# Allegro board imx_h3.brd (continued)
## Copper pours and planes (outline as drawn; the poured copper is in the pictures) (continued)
GND on GND1: 0.15,0.35 0.15,19.29 4.65,19.29 4.65,28.95 0.2,28.95 0.2,60.94 4.7,60.94 4.7,70.63 0.3,70.63 0.3,81.15 4.7,81.15 4.7,81.14 62.81,81.14 62.81,90.02 91.19,90.02 91.19,104.8 109.62,104.8 109.62,54.25 123.5,54.25 123.5,0.31 23.95,0.31 23.95,1.84 16.66,1.84 16.66,0.35 ; 3 cut-outs
GND on INT1: 0.15,0.35 0.15,19.3 4.65,19.3 4.65,28.95 0.2,28.95 0.2,60.97 4.7,60.97 4.7,70.62 0.3,70.62 0.3,81.14 62.81,81.14 62.81,90.02 91.19,90.02 91.19,104.8 109.62,104.8 109.62,54.25 123.5,54.25 123.5,0.31 23.95,0.31 23.95,1.84 16.66,1.84 16.66,0.35 ; 60 cut-outs
GND on PWR: 4.7,60.97 4.7,70.62 0.3,70.62 0.3,81.15 11.87,81.15 11.87,81.14 62.78,81.14 62.78,90.03 70.05,90.03 70.05,73.72 30.12,73.72 26.55,70.14 26.55,69.51 11.58,69.51 11.58,54.67 10.75,54.67 10.75,12.21 4.41,12.21 4.41,0.35 0.15,0.35 0.15,19.31 4.65,19.31 4.65,28.95 0.2,28.94 0.2,60.97
GND on PWR: 23.94,0.3 23.94,1.85 20.04,1.85 20.04,13.74 44.77,13.74 44.77,4.1 55.62,4.1 55.62,6.47 78.15,6.47 78.15,0.3
GND on GND2: 0.3,0.35 0.3,19.31 4.65,19.31 4.65,28.96 0.2,28.96 0.2,60.97 4.85,60.97 4.85,70.62 0.3,70.62 0.3,81.14 62.78,81.14 62.78,90.08 91.19,90.08 91.19,104.8 109.62,104.8 109.62,54.21 123.5,54.21 123.5,0.31 23.95,0.31 23.95,1.85 16.65,1.85 16.65,0.35 ; 3 cut-outs
VBUS_OTG on TOP: 84,11.14 84,3.37 86.36,3.37 86.36,11.14
VBUS_OTG on PWR: 78.23,0.3 78.23,6.47 86.38,6.47 86.38,3.3 98.83,3.3 98.83,18.03 104.78,18.03 104.78,26.39 104.83,26.39 104.83,33.34 100.34,33.34 100.34,45.94 102.95,48.54 102.95,54.13 104.04,54.13 104.04,63.47 105.22,63.47 105.22,36.82 123.37,36.82 123.37,0.3
VDD_4P2 on TOP: 62.87,36.51 65.04,34.34 65.04,33.56 65.37,33.24 65.79,33.24 66.35,32.68 66.35,32.16 64.03,32.16 63.68,32.52 63.68,34.29 62.94,35.03 62.94,35.04 62.07,35.91 61.27,35.91 61.27,36.51
(no net) on BOTTOM: 0.15,0.35 0.15,19.29 4.65,19.29 4.65,28.95 0.2,28.95 0.2,60.94 4.7,60.94 4.7,70.63 0.3,70.63 0.3,81.15 4.7,81.15 4.7,81.14 62.81,81.14 62.81,90.02 91.19,90.02 91.19,104.8 109.62,104.8 109.62,54.25 123.5,54.25 123.5,0.31 23.95,0.31 23.95,1.84 16.66,1.84 16.66,0.35 ; 78 cut-outs
DCDC_VDDA_1V8 on TOP: 76,56.55 76,45.25 77.18,45.25 77.18,56.55
DCDC_VDDA_1V8 on TOP: 58.8,45.37 58.8,42.38 60.65,42.38 60.65,46.2 59.63,46.2
DCDC_VDDA_1V8 on TOP: 54.75,46.9 54.75,43.84 56.66,43.84 56.66,46.9
DCDC_VDDA_1V8 on BOTTOM: 71.39,58.44 71.39,58.23 72.28,57.34 73.41,57.34 74,56.75 74.84,56.75 75.53,56.06 75.53,44.06 77.46,44.06 77.46,55.74 74.75,58.44
DCDC_VDDA_1V8 on PWR: 53.43,41.57 53.43,46.59 56.24,46.59 57.4,47.74 57.4,48.4 57.12,48.69 57.12,53.31 56.72,53.71 56.72,55.35 56.79,55.43 56.79,58.31 58.88,58.31 61.16,60.59 76.73,60.59 76.73,58.56 79.4,55.89 79.4,45.62 75.68,41.9 72.23,41.9 70.99,43.13 64.44,43.13 62.87,41.57
DCDC_VDDD_1V2 on TOP: 57.53,46.84 57.53,44.62 58.39,44.62 58.39,45 59.23,45.84 59.23,46.76 59.2,46.79 58.5,46.79 58.39,46.68 58.39,46.84
DCDC_VDDD_1V2 on INT1: 58.59,41.31 58.93,41.31 63.63,36.61 72.91,36.61 72.91,41.31 68.36,41.31 67.66,42.01 67.66,47.5 59.84,47.5 59.84,47.5 59.54,47.5 59.54,47.6 58.73,48.41 56.55,48.41 56.55,44.44 58.59,42.39 ; 4 cut-outs
DCDC_VDDIO_3V3 on TOP: 63.48,51.12 64.58,51.12 65.09,50.61 67.86,50.61 67.86,43.63 61.6,43.63 61.6,44.2 63.05,44.2 63.05,49.1 62.99,49.16 62.99,50.63
DCDC_VDDIO_3V3 on TOP: 64.68,62.93 64.68,56.78 50.71,56.78 50.71,62.93 ; 3 cut-outs
DCDC_VDDIO_3V3 on TOP: 54.65,48.48 54.65,48.46 54.51,48.31 54.51,47.43 54.74,47.2 56.59,47.2 56.59,47.79 57.42,47.79 57.42,48.31 57.09,48.31 56.45,48.95 56.01,48.95 55.77,48.71 55.54,48.71 55.31,48.48
DCDC_VDDIO_3V3 on TOP: 95.08,44.47 98.65,48.05 99.5,48.05 102.75,51.3 102.75,51.95 103.7,51.95 103.7,47.75 102.55,46.6 101.05,46.6 97,42.55
DCDC_VDDIO_3V3 on BOTTOM: 26.34,47.16 26.34,48.97 31.3,53.93 33.54,53.93 37.85,58.25 45.36,58.25 47.66,55.94 47.66,49.77 39.13,49.77 39.15,49.78 30.69,49.78 28.06,47.16
DCDC_VDDIO_3V3 on BOTTOM: 62.93,42.79 62.93,42.38 63.46,41.85 63.46,39.78 63.65,39.59 63.91,39.59 64.53,40.22 64.53,40.85 64.73,41.06 66.62,41.06 66.62,43.61 64.56,43.61 64.56,43.71 63.64,44.63 61.64,44.63 61.58,44.57 61.58,43.74 62.35,42.97 62.77,42.97
DCDC_VDDIO_3V3 on INT1: 64.73,62.93 64.73,49.2 54.82,49.2 50.71,53.31 50.71,62.93 ; 15 cut-outs
DCDC_VDDIO_3V3 on PWR: 89.36,36.35 88.29,37.42 88.29,43.1 86.02,45.37 86.02,49.81 83.68,52.16 79.52,52.16 79.52,55.94 76.89,58.57 76.89,60.69 61.08,60.69 58.81,58.42 56.56,58.42 56.56,56.19 57.01,55.75 57.01,48.59 57.3,48.3 57.3,47.86 56.02,46.59 55.45,46.59 55.45,46.57 53.42,46.57 53.42,41.5 62.96,41.5 64.43,42.97 67.49,42.97 65.88,41.37 65.88,38.05 47.18,38.05 45.88,39.35 45.88,56.82 39.7,63 39.7,69.98 68.98,69.98 69.94,69.02 69.94,67.96 72.41,65.49 82.08,65.49 86.56,61.01 86.56,53.09 89.18,50.46 89.18,49.36 95.61,42.93 95.61,36.35
DCDC_VDDIO_3V3 on PWR: 16.29,47.13 28.19,47.13 28.19,48.59 14.37,48.59 14.37,28.37 25.95,28.37 25.95,32.16 20.34,37.77 16.29,37.77
DDR2_VREF on TOP: 55.57,56.18 65.86,56.18 67.7,54.34 68.8,54.34 68.8,50.75 65.19,50.75 64.68,51.26 63.62,51.26 62.9,50.55 62.9,48.75 61.75,47.6 59,47.6 58.16,48.45 55.57,48.45 ; 2 cut-outs
DDR2_VREF on BOTTOM: 56.45,58.25 56.45,55.88 58.25,55.88 58.25,58.25
DEBUG_GND on BOTTOM: 113.4,0.3 113.4,7.06 123.09,7.06 123.09,0.3
DUAL_GND on BOTTOM: 21.88,19.5 21.88,7.78 40.58,7.78 40.58,19.5 ; 1 cut-out
FEC_A3V3 on BOTTOM: 28.2,45.42 28.2,41.34 29.2,40.34 29.91,40.34 30.44,39.82 33.15,39.82 33.15,40.78 31.45,42.48 31.45,45.42
FEC_A3V3 on PWR: 28.49,44.38 28.49,42.21 30.59,40.12 38.63,40.12 38.63,44.38
LI-ION_BATTERY on TOP: 63.77,38.19 60.38,38.19 59.84,37.65 59.84,36.57 62.94,36.57 65.5,34.02 65.5,33.38 66.7,32.17 66.7,29.68 69.61,29.68 69.61,31.03 71.19,32.61 71.19,35.84 73.64,35.84 73.64,35.61 74.09,35.16 74.92,35.16 74.92,36.03 74.39,36.54 73.17,36.54 73.17,37.37 73.91,38.1 73.91,38.93 73.42,38.93 71.09,36.6 64.82,36.6 63.77,37.65
LI-ION_BATTERY on BOTTOM: 61.14,42.17 61.14,37.51 61.82,36.84 62.02,36.84 62.02,42.17
N21906184 on TOP: 10.78,13.58 10.78,18.05 16.64,18.05 16.64,0.35 0.15,0.35 0.15,13.58
N21906184 on PWR: 10.78,19.95 10.78,15.09 10.76,15.09 10.76,12.18 4.52,12.18 4.52,0.35 16.64,0.35 16.64,2.03 19.61,2.03 19.61,19.95
N27773305 on BOTTOM: 90.86,14.86 90.86,10.81 95.82,10.81 95.82,14.86
N29175701 on TOP (solid shape): 8.23,28.56 8.87,28.56 8.87,28.56 9.66,28.56 9.67,27.57 7.54,27.57 7.54,28.56 8.23,28.56
N29175849 on TOP (solid shape): 8.92,70.24 9.71,70.24 9.72,69.25 7.6,69.25 7.6,70.24 8.29,70.24 8.29,70.45 8.92,70.45
N29213138 on TOP (solid shape): 0.94,69.57 1.08,69.57 1.08,68.97 0.96,68.97 0.96,62.37 2.3,62.37 2.3,62.82 1.8,62.82 1.8,63.12 3.41,63.12 3.41,62.82 2.8,62.82 2.8,61.87 0.21,61.87 0.21,69.57 0.34,69.57 0.34,69.58 0.94,69.58
N29213145 on TOP (solid shape): 0.89,27.9 1.03,27.9 1.03,27.3 0.9,27.3 0.9,20.7 2.25,20.7 2.25,21.15 1.75,21.15 1.75,21.45 3.35,21.45 3.35,21.15 2.75,21.15 2.75,20.2 0.15,20.2 0.15,27.9 0.29,27.9 0.29,27.9 0.89,27.9

Small or netless copper shapes (teardrops, artwork), in the pictures only: 2 on BOTTOM

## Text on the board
BOTTOM: 30014012-01_A | 6
Ref Des/Silkscreen Bottom: GND | MC12311 | 868MHz RF | NAND Flash | i.MX28 | Battery | POWER | DDR2 | NFC antenna | JTAG port | MC1322x | ZigBee RF
TOP: 30014012-01_A | 1
Ref Des/Silkscreen Top: NTC | S1-2: | S1-1: | ON: Recovery - boot from USB | OFF : Boot from NAND | ON: Force 4.2V from Battery | OFF: Auto detect 4.2V | GND | Li-Ion Battery | NFC antenna conn. | LCD Extension port | Rev. 2 | 5V | PSWITCH | RESET | i.MX28 Home Health Hub | Reference Platform
GND1: 2
INT1: 3
PWR: 4
GND2: 5
DIMENSION: Layers - Dielectric Thickness | 1-2 6.95 mils | 3-4 17.6 mils | 4-5 10 mils | 5-6 6.95 mils | 2-3 10 mils | 10 SECONDS | OF AN INK STAMP
DISPLAY_TOP: 2. BOARD STACKUP : SEE DETAIL A | 4. MINIMUM CONDUCTIVE WIDTH/SPACING 0.1mm/0.1mm | 4. PLATING FINISH - BOTH SIDES ENIG | 3. FINISHED BOARD THICKNESS : 1.5mm | 1. TARGET TRACE IMPEDANCE : | (ELECTROLESS NICKEL IMMERSION GOLD) | 120um width, single ended : 75 Ohm | 150um width, 100um gap, differential : 90 Ohm | 120um width, 120um gap, differential : 100 Ohm | 0.5080-0.232 um OF GOLD OVER | 0.5080-0.232 um OF NICKEL | 13. DRCs MUST BE RUN ON THE GERBER BEFORE BUILDING BOARDS | 11. THE PWB WILL BE MARKED LEAD FREE BY USE OF AN INK STAMP | 10. SUPPLIER MARKINGS : CONSULT FREESCALE | 12. THE PWB WILL BE MARKED LEAD FREE PROCESS COMPATIBLE BY USE | 13. FINISHED PCB MUST BE PANELIZED FOR ASSEMBY | 6. THE PWB  MUST BE LEAD FREE ASSEMBLY COMPATIBLE AND MUST BE | 7. SOLDERMASK - GREEN COLOR, BOTH SIDES | 8. SILKSCREEN - WHITE, BOTH SIDES, NO SILK ON PADS | 9. PRINTED CIRCUIT BOARD IS TO BE INDIVIDUALLY BAGGED | 5. BASE MATERIAL - LAMINATE AND PREPREG SHALL MEET | TO HANDLE A MINIMUM OF 5 CYCLES AT 260 DEGREES CELSIUS FOR | IPC4101A-94 | MAXIMUM HALOGEN CONTENT - 0.10ppm | TG - GREATER THAN OR EQUAL TO 150 DEGREES CELSIUS | Td - GREATER THAN OR EQUAL TO 330 DEGREES CELSIUS
User.12: FIGURE | SIZE | 0.3048 | 0.889 | 0.9398 | 0.9652 | 1.016 | 1.3462 | 1.5748 | 2.286 | 3.2004 | 1.1176 | 1.6002 | 2.3876 | 2.9972 | 3.2512 | 0.8636x0.762 | 1.4986x0.8382 | 2.032x1.016 | 4.191x1.016 | 1.2446x0.889 | DRILL CHART: TOP to BOTTOM | ALL UNITS ARE IN MILLIMETERS | TOLERANCE | +0.0508/-0.0508 | +0.0762/-0.0762 | PLATED | NON-PLATED | QTY | 1 | 2074 | 22 | 8 | 4 | 2 | 3
